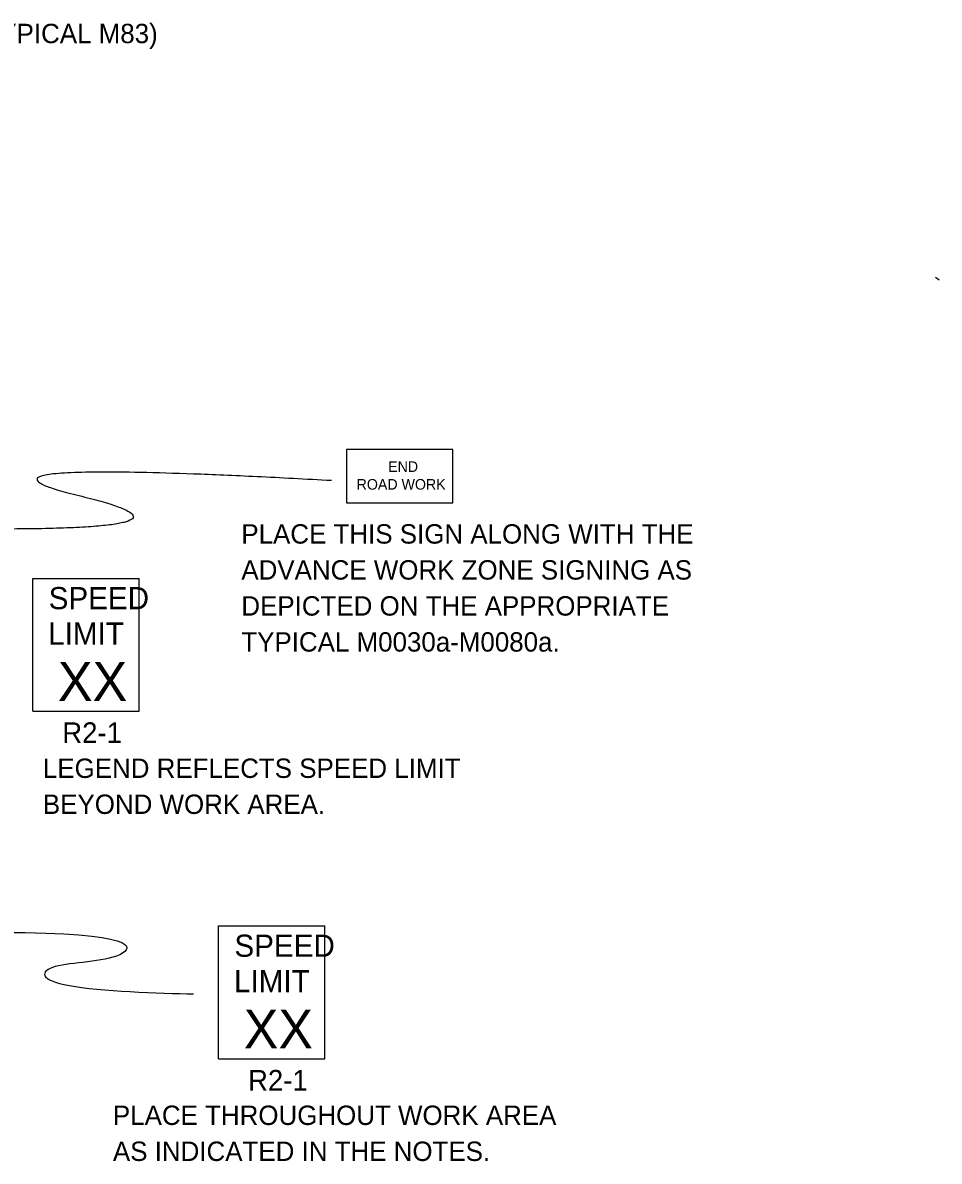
# Model space of a CAD drawing. Extents: x 15261 to 18126, y 1908 to 6555.
# Drawn here: x 15686.1 to 16017.1, y 2906 to 3317.1 of the extents above; entities that cross this region are included whole.
import ezdxf

# ---------------------------------------------------------------- set-up
doc = ezdxf.new("R2010")
doc.units = 0
doc.layers.add('TRAFFIC_SIGNS_PR', color=7, linetype='Continuous')
doc.layers.add('TYPICAL_TEXT_DIMEN_PR', color=7, linetype='Continuous')

msp = doc.modelspace()

# ---------------------------------------------------------------- linework, layer by layer
at = {"layer": 'TRAFFIC_SIGNS_PR'}
for p, q in [((15689.66, 3116.46), (15728.06, 3116.46)), ((15689.66, 3068.46), (15689.66, 3116.46)), ((15728.06, 3068.46), (15728.06, 3116.46)), ((15689.66, 3068.46), (15728.06, 3068.46)), ((15756.76, 2990.94), (15795.16, 2990.94)), ((15756.76, 2942.94), (15756.76, 2990.94)), ((15795.16, 2942.94), (15795.16, 2990.94)), ((15756.76, 2942.94), (15795.16, 2942.94))]:
    msp.add_line(p, q, dxfattribs=at)
msp.add_lwpolyline([(15803.06, 3143.76), (15841.46, 3143.76), (15841.46, 3162.96), (15803.06, 3162.96)], close=True, dxfattribs=at)
msp.add_open_spline([(15797.61, 3151.75), (15650.05, 3159.98), (15763.95, 3132.4), (15650.5, 3134.57)], degree=2, dxfattribs=at)
at = {"layer": 'TYPICAL_TEXT_DIMEN_PR'}
msp.add_line((16015.78, 3225.17), (16017.12, 3224.27), dxfattribs=at)
msp.add_open_spline([(15678.45, 2988.61), (15726.92, 2988.61), (15726.92, 2977.86), (15692, 2977.86), (15692, 2968.14), (15735.61, 2966.65), (15747.74, 2966.39)], degree=3, dxfattribs=at)

# ---------------------------------------------------------------- texts
at = {"layer": 'TRAFFIC_SIGNS_PR'}
for s, height, p in [('END', 3.831, (15818.06, 3154.89)), ('ROAD WORK', 3.831, (15806.67, 3148.5)), ('PLACE THIS SIGN ALONG WITH THE', 7, (15765.03, 3129.01)), ('ADVANCE WORK ZONE SIGNING AS', 7, (15765.03, 3116.01)), ('SPEED', 8, (15695.43, 3105.32)), ('DEPICTED ON THE APPROPRIATE', 7, (15765.03, 3103.01)), ('LIMIT', 8, (15695.27, 3092.52)), ('TYPICAL M0030a-M0080a.', 7, (15765.03, 3090.01)), ('XX', 14.031, (15698.78, 3072.22)), ('R2-1', 7.44, (15700.34, 3057.02)), ('LEGEND REFLECTS SPEED LIMIT', 7, (15693.35, 3044.39)), ('BEYOND WORK AREA.', 7, (15693.35, 3031.39)), ('SPEED', 8, (15762.53, 2979.8)), ('LIMIT', 8, (15762.37, 2967)), ('XX', 14.031, (15765.88, 2946.69)), ('R2-1', 7.44, (15767.44, 2931.5)), ('PLACE THROUGHOUT WORK AREA', 7, (15718.64, 2919.07)), ('AS INDICATED IN THE NOTES.', 7, (15718.64, 2906.07))]:
    msp.add_text(s, height=height, dxfattribs=at).set_placement(p)
at = {"layer": 'TYPICAL_TEXT_DIMEN_PR'}
msp.add_text('IS CLOSED FIRST AND THEN BY SHIFTING TRAFFIC TO THE LEFT LANE. (SEE TYPICAL M83)', height=7, dxfattribs=at).set_placement((15319.26, 3309.72))

doc.saveas('drawing.dxf')
